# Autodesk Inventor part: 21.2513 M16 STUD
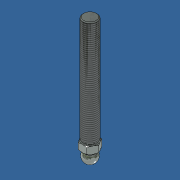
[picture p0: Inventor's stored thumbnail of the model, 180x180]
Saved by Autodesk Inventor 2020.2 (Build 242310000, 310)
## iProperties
Created: 2015-07
Document SubType Name: Modeling
Designer: Oster
Material: Steel
Description: Kugelschraube M16x120 MT
Part Number: 21.2513 M16 STUD
Mass: 219.155 g
Surface Area: 75.4544 cm^2
Volume: 27.9178 cm^3
Density: 7.85 g/cm^3
Appearance: Zink
Beschreibung: Kugelschraube M16x120 MT
Bezeichnung: Kugelschraube M16x120 MT
Artikelnr: 212904/0
AIMD_ORIGIN: 00000478
Lieferantennr: 72401
Zeichnungsnr: 21-2904-0FZ.001
MiniTec_ID: 212904/0
Teileart: K
Lieferant: MiniTec
Title: Kugelschraube M16x120 MT
Author: Andy Moles
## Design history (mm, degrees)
sketch "Sketch1"
  geometry: L1 (0, -7.5)-(0, 7.5); A1 r 7.5 centre (0, 0) between (0, -7.5) and (0, 7.5); 1 further point
  constraints: 2 end point, 2 point on circle, 1 centre point, 1 coincident, 1 midpoint, 1 vertical
  dimensions: "d5" = 15 distance of L1.start L1.end
revolve "Revolution1" sketch "Sketch1" stored, may be unused: angle "d1" = 90 deg
sketch "Sketch2"
  geometry: C1 r 6 at (0, 0); 1 further point
  constraints: 1 centre point, 1 coincident
  dimensions: "d2" = 12 diameter of C1
extrude "Extrusion1" join sketch "Sketch2" distance "d3" = 7; taper "d4" = 0 deg
sketch "Sketch3"
  geometry: L1 (-4.907, 8.5)-(4.907, 8.5); L2 (4.907, 8.5)-(9.815, 0); L3 (9.815, 0)-(4.907, -8.5); L4 (4.907, -8.5)-(-4.907, -8.5); L5 (-4.907, -8.5)-(-9.815, 0); L6 (-9.815, 0)-(-4.907, 8.5); C1 r 6 at (0, 0) reference; 1 further point
  constraints: 12 end point, 5 equal length, 1 horizontal, 1 horizontal alignment, 1 midpoint, 1 parallel, 1 vertical alignment
  dimensions: "d6" = 120 deg angle of L6 L5; "d7" = 120 deg angle of L1 L6; "d8" = 17 distance between parallel lines of L4 L1
extrude "Extrusion2" join sketch "Sketch3" distance "d9" = 8; taper "d10" = 0 deg
sketch "Sketch4"
  geometry: C1 r 8 at (0, 0); 1 further point
  constraints: 1 centre point, 1 coincident
  dimensions: "d11" = 16 diameter of C1
extrude "Extrusion3" join sketch "Sketch4" distance "d12" = 120; taper "d13" = 0 deg
thread "Thread1" dims "d14" = 148, "d15" = 2
chamfer "Chamfer1" distance "d16" = 1; stored, may be unused: second distance "d17" = 2, angle "d18" = 45 deg
sketch "Skizze5"
  geometry: L1 (0, -36)-(0, 163.5) reference; L2 (-8.222, 15.169)-(-10.594, 13.8); L3 (-8.222, 15.169)-(-10.323, 15.169); L4 (-10.323, 15.169)-(-10.594, 13.8); L5 (-9.815, 15)-(-4.907, 15) reference; L6 (-4.907, 7)-(-4.907, 15) reference; L7 (-9.815, 7)-(-4.907, 7) reference; L8 (-9.815, 7)-(-9.815, 15) reference; L9 (-12.881, 11)-(12.669, 11); L10 (-8.222, 6.831)-(-10.594, 8.2); L11 (-8.222, 6.831)-(-10.323, 6.831); L12 (-10.323, 6.831)-(-10.594, 8.2); L13 (-7.2, 15)-(-7.2, 15.75); L14 (-7.2, 15.75)-(-8.119, 16.637); L15 (-8.119, 16.637)-(-8.119, 15); L16 (-8.119, 15)-(-7.2, 15); 3 further points
  constraints: 22 end point, 5 point on line, 4 perpendicular, 4 symmetric about line, 1 collinear
  dimensions: "d19" = 60 deg angle of L1 L2; "d20" = 0.75 distance from line of point (-9.815, 14.25) L5; "d22" = 4 distance between parallel lines of L9 L7; "d23" = 7.2 distance between parallel lines of L1 L13; "d24" = 0.75 distance of L13.start L13.end; "d25" = 134 deg angle of L13 L14
revolve "Umdrehung2" sketch "Skizze5" stored, may be unused: angle "d21" = 90 deg
node "Volumenkörper1"
node "Volumenkörpern"
node "Oberflächenkörpern"
node "Projizierte Kontur1"
